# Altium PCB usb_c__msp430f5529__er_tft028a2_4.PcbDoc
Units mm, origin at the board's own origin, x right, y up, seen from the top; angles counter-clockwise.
Board outline 82 x 52 mm, 2 copper layers (Top, Bottom), stack 0 mm thick; 36 components, 35 nets, 241 pads, 100 vias.
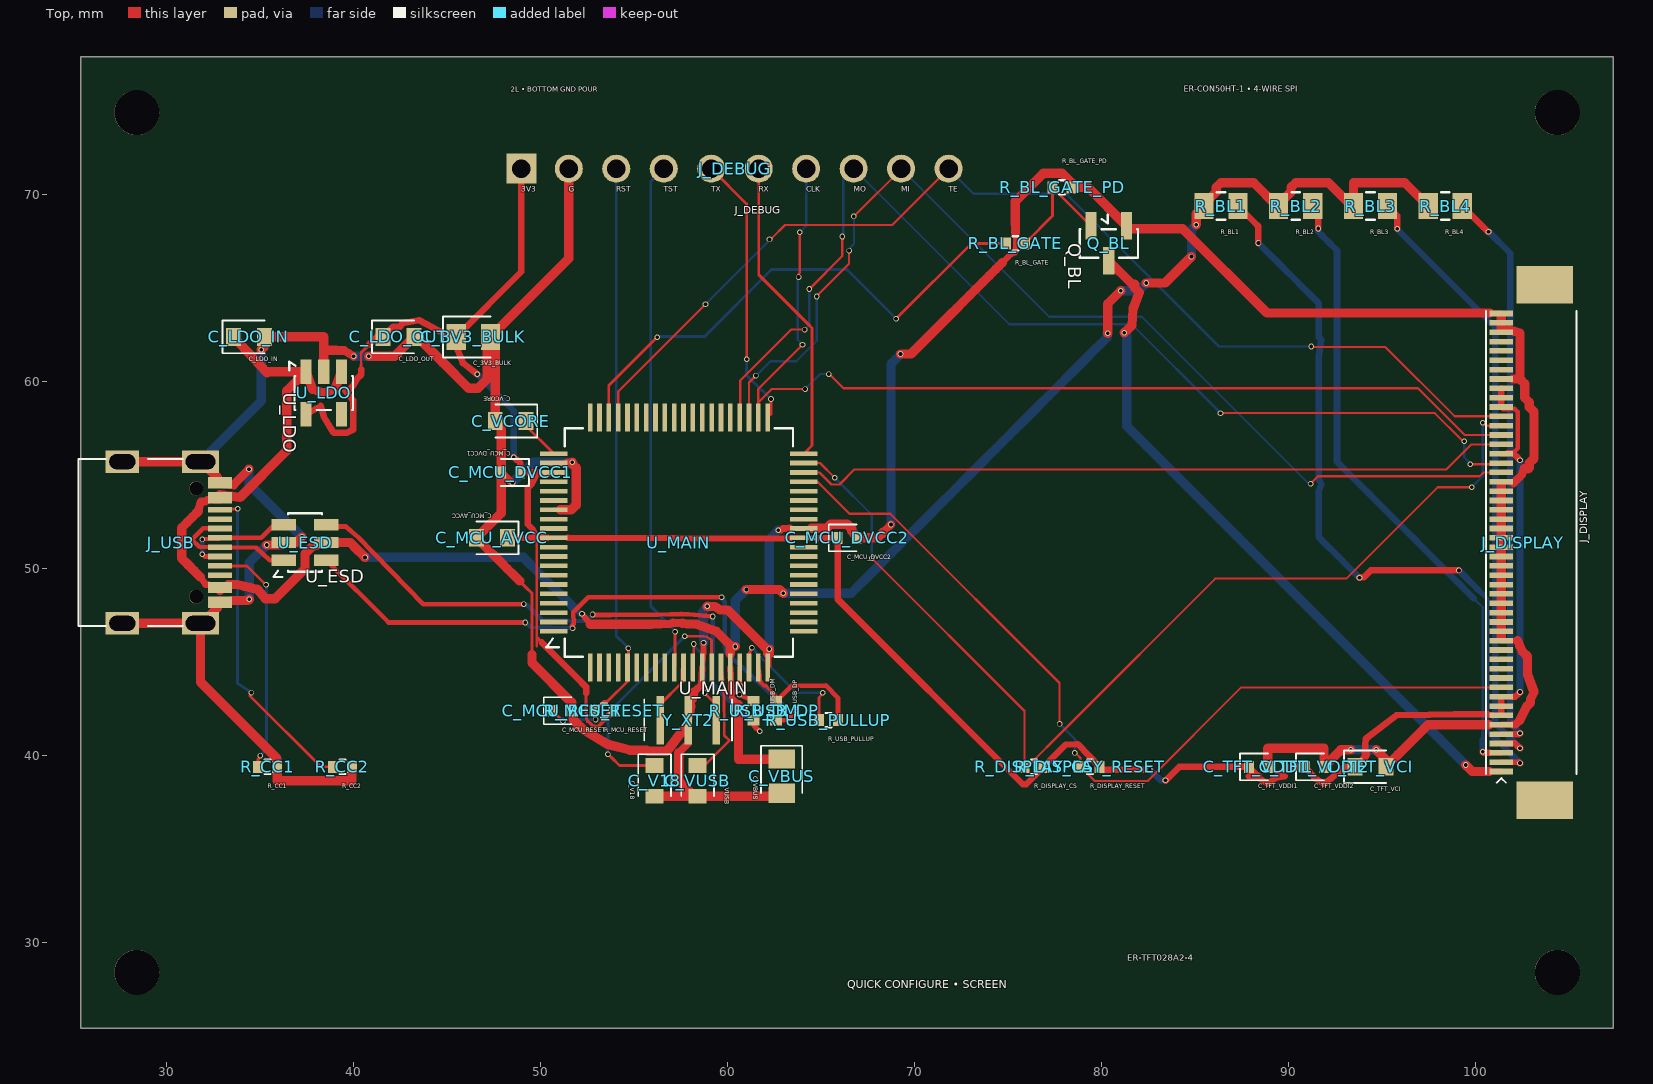
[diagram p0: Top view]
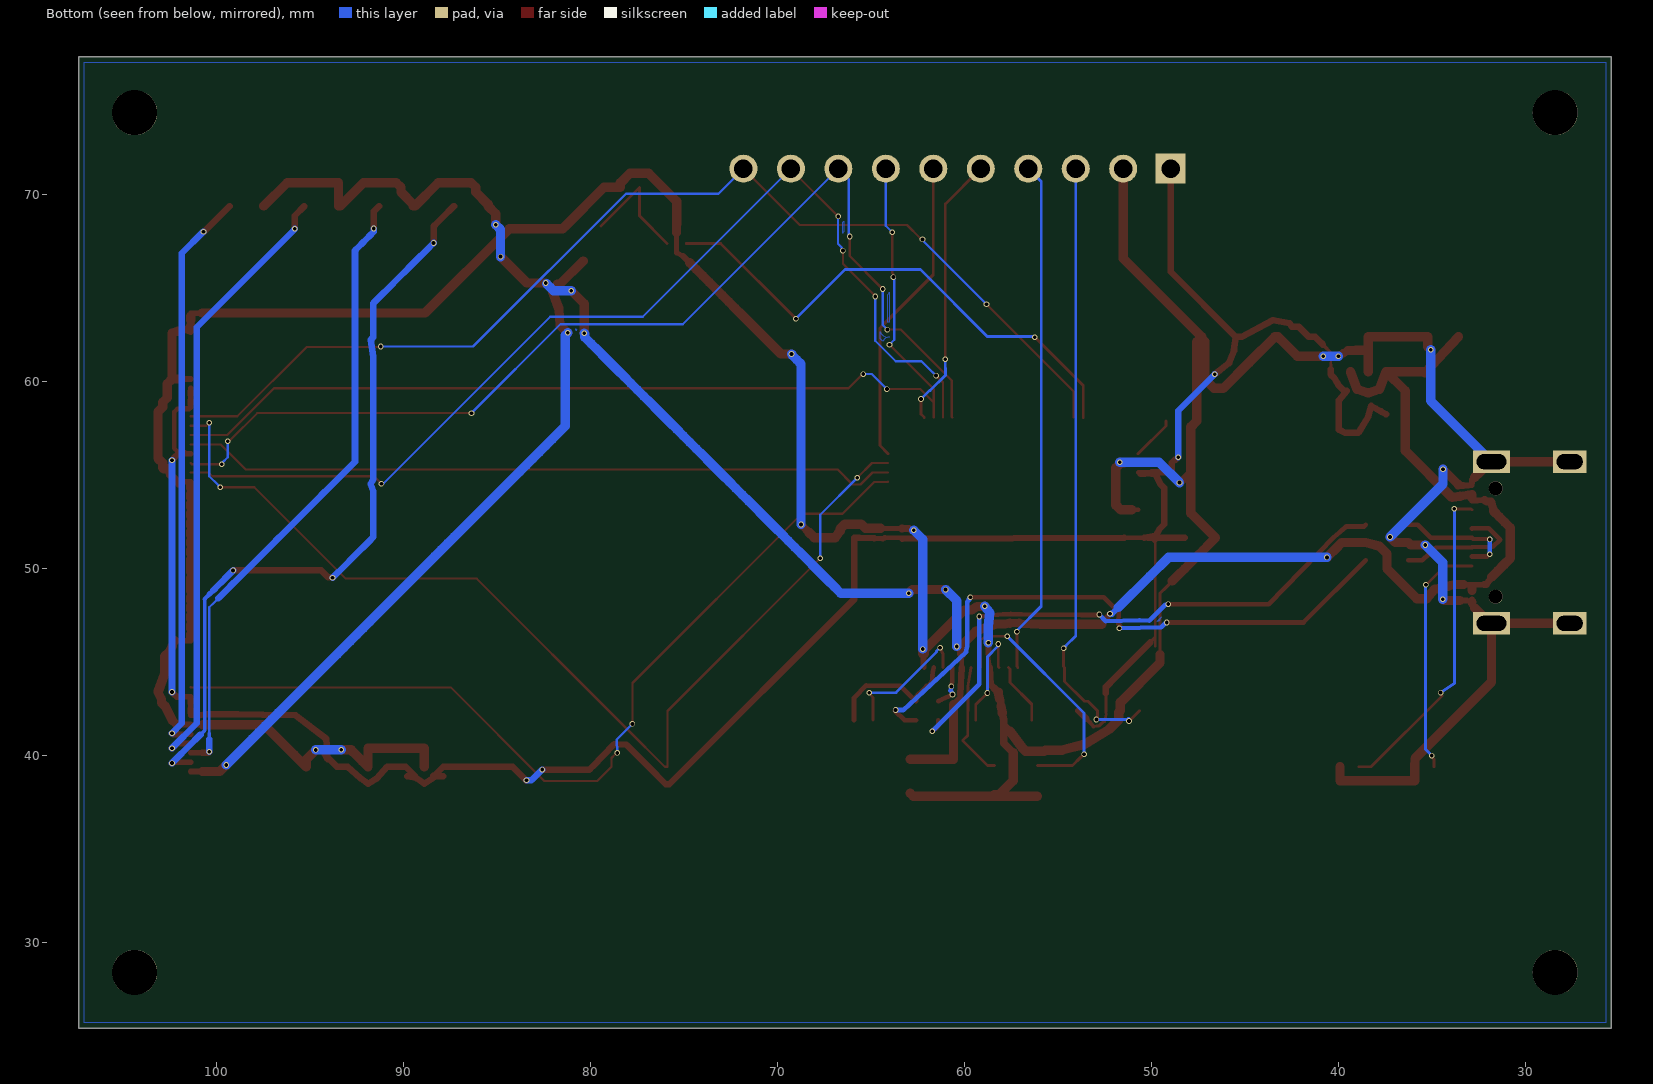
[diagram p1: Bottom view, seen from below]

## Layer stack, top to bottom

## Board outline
25.4,77.4 107.4,77.4 107.4,25.4 25.4,25.4

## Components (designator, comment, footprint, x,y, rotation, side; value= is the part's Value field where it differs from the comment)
C_3V3_BULK "" TSCIRCUIT-2.8500x1.4000mm 46.4,62.4 r0 top
C_LDO_IN "" TSCIRCUIT-2.4500x0.9500mm 34.4,62.4 r0 top
C_LDO_OUT "" TSCIRCUIT-2.4500x0.9500mm 42.4,62.4 r0 top
C_MCU_AVCC "" TSCIRCUIT-2.4500x0.9500mm 47.4,51.65 r180 top
C_MCU_DVCC1 "" TSCIRCUIT-1.5600x0.6400mm 48.4,55.15 r180 top
C_MCU_DVCC2 "" TSCIRCUIT-1.5600x0.6400mm 66.4,51.65 r0 top
C_MCU_RESET "" TSCIRCUIT-1.5600x0.6400mm 51.15,42.4 r0 top
C_TFT_VCI "" TSCIRCUIT-2.4500x0.9500mm 94.4,39.4 r0 top
C_TFT_VDDI1 "" TSCIRCUIT-1.5600x0.6400mm 88.4,39.4 r0 top
C_TFT_VDDI2 "" TSCIRCUIT-1.5600x0.6400mm 91.4,39.4 r0 top
C_V18 "" TSCIRCUIT-0.9500x2.4500mm 56.1,38.65 r270 top
C_VBUS "" TSCIRCUIT-1.4000x2.8500mm 62.9,38.9 r270 top
C_VCORE "" TSCIRCUIT-2.4500x0.9500mm 48.4,57.9 r180 top
C_VUSB "" TSCIRCUIT-0.9500x2.4500mm 58.4,38.65 r270 top
J_DEBUG "" TSCIRCUIT-24.3600x1.5000mm 60.4,71.4 r0 top
J_DISPLAY "" TSCIRCUIT-4.4500x29.5800mm 103,51.4 r90 top
J_USB "" TSCIRCUIT-6.7732x9.8502mm 30.113,51.4 r90 top
Q_BL "" TSCIRCUIT-2.5000x3.3500mm 80.4,67.4 r270 top
R_BL1 "" TSCIRCUIT-2.8500x1.4000mm 86.4,69.4 r0 top
R_BL2 "" TSCIRCUIT-2.8500x1.4000mm 90.4,69.4 r0 top
R_BL3 "" TSCIRCUIT-2.8500x1.4000mm 94.4,69.4 r0 top
R_BL4 "" TSCIRCUIT-2.8500x1.4000mm 98.4,69.4 r0 top
R_BL_GATE "" TSCIRCUIT-1.5600x0.6400mm 75.4,67.4 r0 top
R_BL_GATE_PD "" TSCIRCUIT-1.5600x0.6400mm 77.9,70.4 r0 top
R_CC1 "" TSCIRCUIT-1.5600x0.6400mm 35.4,39.4 r0 top
R_CC2 "" TSCIRCUIT-1.5600x0.6400mm 39.4,39.4 r0 top
R_DISPLAY_CS "" TSCIRCUIT-1.5600x0.6400mm 76.4,39.4 r0 top
R_DISPLAY_RESET "" TSCIRCUIT-1.5600x0.6400mm 79.4,39.4 r0 top
R_MCU_RESET "" TSCIRCUIT-1.5600x0.6400mm 53.4,42.4 r0 top
R_USB_DM "" TSCIRCUIT-0.6400x1.5600mm 61.4,42.4 r90 top
R_USB_DP "" TSCIRCUIT-0.6400x1.5600mm 62.6,42.4 r90 top
R_USB_PULLUP "" TSCIRCUIT-1.5600x0.6400mm 65.4,41.9 r0 top
U_ESD "" TSCIRCUIT-3.6000x2.5000mm 37.4,51.4 r0 top
U_LDO "" TSCIRCUIT-2.5000x3.6000mm 38.4,59.4 r270 top
U_MAIN "" TSCIRCUIT-14.8500x14.8500mm 57.4,51.4 r0 top
Y_XT2 "" TSCIRCUIT-3.4000x2.6000mm 57.9,41.9 r270 top

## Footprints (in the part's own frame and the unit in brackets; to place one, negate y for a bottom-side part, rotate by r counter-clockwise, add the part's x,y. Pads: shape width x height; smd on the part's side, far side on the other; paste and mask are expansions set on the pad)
TSCIRCUIT-0.6400x1.5600mm [mm]
  rect 0.54x0.64 smd: 1(-0.51,0) 2(0.51,0)
  silkscreen extent -0.15,-0.38 0.15,0.38
TSCIRCUIT-0.9500x2.4500mm [mm]
  rect 0.8x0.95 smd: 1(-0.825,0) 2(0.825,0)
  silkscreen extent -1.43,-0.87 0.82,0.87
TSCIRCUIT-1.4000x2.8500mm [mm]
  rect 1.025x1.4 smd: 1(-0.913,0) 2(0.913,0)
  silkscreen extent -1.62,-1.1 0.91,1.1
TSCIRCUIT-1.5600x0.6400mm [mm]
  rect 0.54x0.64 smd: 1(-0.51,0) 2(0.51,0)
  silkscreen extent -0.98,-0.72 0.51,0.72
TSCIRCUIT-2.4500x0.9500mm [mm]
  rect 0.8x0.95 smd: 1(-0.825,0) 2(0.825,0)
  silkscreen extent -1.43,-0.87 0.82,0.87
TSCIRCUIT-2.5000x3.3500mm [mm]
  rect 1.475x0.6 smd: 1(-0.938,-0.95) 2(-0.938,0.95) 3(0.937,0)
  silkscreen extent -1.54,-1.56 0.76,1.56
TSCIRCUIT-2.5000x3.6000mm [mm]
  rect 1.325x0.6 smd: 1(-1.137,-0.95) 2(-1.137,0) 3(-1.137,0.95) 4(1.138,0.95) 5(1.138,-0.95)
  silkscreen extent -1.69,-1.84 0.91,1.56
TSCIRCUIT-2.8500x1.4000mm [mm]
  rect 1.025x1.4 smd: 1(-0.913,0) 2(0.913,0)
  silkscreen extent -1.63,-1.1 0.91,1.1
TSCIRCUIT-3.4000x2.6000mm [mm]
  rect 2.6x0.4 smd: 1(0,1.5) 2(0,0) 3(0,-1.5)
  silkscreen extent -1.1,-2.35 1.1,2.35
TSCIRCUIT-3.6000x2.5000mm [mm]
  rect 1.325x0.6 smd: 1(-1.137,-0.95) 2(-1.137,0) 3(-1.137,0.95) 4(1.138,0.95) 5(1.138,0) 6(1.138,-0.95)
  silkscreen extent -1.69,-1.84 0.91,1.56
TSCIRCUIT-4.4500x29.5800mm [mm]
  rect 0.3x1.25 smd: 1(-12.25,1.6) 2(-11.75,1.6) 3(-11.25,1.6) 4(-10.75,1.6) 5(-10.25,1.6) 6(-9.75,1.6) 7(-9.25,1.6) 8(-8.75,1.6) 9(-8.25,1.6) 10(-7.75,1.6) 11(-7.25,1.6) 12(-6.75,1.6) 13(-6.25,1.6) 14(-5.75,1.6) 15(-5.25,1.6) 16(-4.75,1.6) 17(-4.25,1.6) 18(-3.75,1.6) 19(-3.25,1.6) 20(-2.75,1.6) 21(-2.25,1.6) 22(-1.75,1.6) 23(-1.25,1.6) 24(-0.75,1.6) 25(-0.25,1.6) 26(0.25,1.6) 27(0.75,1.6) 28(1.25,1.6) 29(1.75,1.6) 30(2.25,1.6) 31(2.75,1.6) 32(3.25,1.6) 33(3.75,1.6) 34(4.25,1.6) 35(4.75,1.6) 36(5.25,1.6) 37(5.75,1.6) 38(6.25,1.6) 39(6.75,1.6) 40(7.25,1.6) 41(7.75,1.6) 42(8.25,1.6) 43(8.75,1.6) 44(9.25,1.6) 45(9.75,1.6) 46(10.25,1.6) 47(10.75,1.6) 48(11.25,1.6) 49(11.75,1.6) 50(12.25,1.6)
  rect 2x3 smd: 51(13.79,-0.725) 52(-13.79,-0.725)
  silkscreen extent -12.85,-2.43 12.4,2.42
TSCIRCUIT-6.7732x9.8502mm [mm]
  rect 0.3x1.3 smd: 1(-3.35,-2.737) 2(-3.05,-2.737) 3(-2.55,-2.737) 4(-2.25,-2.737) 5(-1.75,-2.737) 6(-1.25,-2.737) 7(-0.75,-2.737) 8(-0.25,-2.737) 9(0.25,-2.737) 10(0.75,-2.737) 11(1.25,-2.737) 12(1.75,-2.737) 13(2.55,-2.737) 14(2.25,-2.737) 15(3.35,-2.737) 16(3.05,-2.737)
  rect 1.2x2 hole 0.8 slot 1.6 at 90 deg: 17(-4.325,-1.693) 18(4.325,-1.693)
  rect 1.2x1.8 hole 0.8 slot 1.4 at 90 deg: 19(4.325,2.487) 20(-4.325,2.487)
  round 0.75 hole 0.75 unplated: NPTH-1(-2.9,-1.468) NPTH-2(2.9,-1.468)
  silkscreen extent -4.47,-0.75 4.47,4.83
TSCIRCUIT-14.8500x14.8500mm [mm]
  rect 1.475x0.25 smd: 1(-6.687,-4.75) 2(-6.687,-4.25) 3(-6.687,-3.75) 4(-6.687,-3.25) 5(-6.687,-2.75) 6(-6.687,-2.25) 7(-6.687,-1.75) 8(-6.687,-1.25) 9(-6.687,-0.75) 10(-6.687,-0.25) 11(-6.687,0.25) 12(-6.687,0.75) 13(-6.687,1.25) 14(-6.687,1.75) 15(-6.687,2.25) 16(-6.687,2.75) 17(-6.687,3.25) 18(-6.687,3.75) 19(-6.687,4.25) 20(-6.687,4.75) 41(6.687,4.75) 42(6.687,4.25) 43(6.687,3.75) 44(6.687,3.25) 45(6.687,2.75) 46(6.687,2.25) 47(6.687,1.75) 48(6.687,1.25) 49(6.687,0.75) 50(6.687,0.25) 51(6.687,-0.25) 52(6.687,-0.75) 53(6.687,-1.25) 54(6.687,-1.75) 55(6.687,-2.25) 56(6.687,-2.75) 57(6.687,-3.25) 58(6.687,-3.75) 59(6.687,-4.25) 60(6.687,-4.75)
  rect 0.25x1.475 smd: 21(-4.75,6.687) 22(-4.25,6.687) 23(-3.75,6.687) 24(-3.25,6.687) 25(-2.75,6.687) 26(-2.25,6.687) 27(-1.75,6.687) 28(-1.25,6.687) 29(-0.75,6.687) 30(-0.25,6.687) 31(0.25,6.687) 32(0.75,6.687) 33(1.25,6.687) 34(1.75,6.687) 35(2.25,6.687) 36(2.75,6.687) 37(3.25,6.687) 38(3.75,6.687) 39(4.25,6.687) 40(4.75,6.687) 61(4.75,-6.687) 62(4.25,-6.687) 63(3.75,-6.687) 64(3.25,-6.687) 65(2.75,-6.687) 66(2.25,-6.687) 67(1.75,-6.687) 68(1.25,-6.687) 69(0.75,-6.687) 70(0.25,-6.687) 71(-0.25,-6.687) 72(-0.75,-6.687) 73(-1.25,-6.687) 74(-1.75,-6.687) 75(-2.25,-6.687) 76(-2.75,-6.687) 77(-3.25,-6.687) 78(-3.75,-6.687) 79(-4.25,-6.687) 80(-4.75,-6.687)
  silkscreen extent -7.09,-6.11 6.11,6.11
TSCIRCUIT-24.3600x1.5000mm [mm]
  rect 1.6x1.6 hole 1: 1(-11.43,0)
  round 1.5 hole 1: 2(-8.89,0) 3(-6.35,0) 4(-3.81,0) 5(-1.27,0) 6(1.27,0) 7(3.81,0) 8(6.35,0) 9(8.89,0) 10(11.43,0)

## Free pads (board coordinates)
  round 2.4 hole 2.4 unplated: NPTH-3(28.4,28.4) NPTH-4(104.4,28.4) NPTH-5(28.4,74.4) NPTH-6(104.4,74.4)

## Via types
v1: diameter 0.3, hole 0.2, Top to Bottom, 100 vias

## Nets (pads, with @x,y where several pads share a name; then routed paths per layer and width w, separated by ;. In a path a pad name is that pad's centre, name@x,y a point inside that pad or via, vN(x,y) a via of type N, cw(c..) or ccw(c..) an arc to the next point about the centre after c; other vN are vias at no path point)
".J_DEBUG > .pin4 to .U_MAIN > .pin71": J_DEBUG.4 U_MAIN.71 | length 27.5
  Top w0.15: U_MAIN.71 57.197,44.759 v1(57.197,46.62)
  Bottom w0.15: J_DEBUG.4 55.895,70.705 55.895,48.203 55.895,47.992 57.198,46.689 57.198,46.676 v1(57.197,46.62)
".J_DEBUG > .pin5 to .U_MAIN > .pin40": J_DEBUG.5 U_MAIN.40 | length 14.7
  Top w0.15: J_DEBUG.5 61.026,69.504 61.026,61.435 v1@61.026,61.2 ; U_MAIN.40 62.329,58.266 v1(62.329,59.08)
  Bottom w0.15: v1(61.026,61.2) 61.023,60.347 61.837,59.536 61.872,59.537 62.2,59.209 v1(62.329,59.08)
".J_DEBUG > .pin6 to .U_MAIN > .pin41": J_DEBUG.6 U_MAIN.41 | length 16.6
  Top w0.15: J_DEBUG.6 61.67,65.728 64.377,63.021 64.521,62.878 64.521,56.721 64.521,56.583 U_MAIN.41
BACKLIGHT_ANODE_1: J_DISPLAY.2 R_BL1.2 | length 40.9
  Top w0.3: J_DISPLAY.2 101.71,39.65 102.019,39.65 v1@102.329,39.65
  Top w0.35: R_BL1.2 87.531,69.182 87.749,68.964 87.967,68.746 88.185,68.528 88.403,68.31 88.403,68.015 88.403,67.719 v1(88.403,67.424) ; v1(93.81,49.513) 93.829,49.532 94.038,49.532 94.225,49.72 94.413,49.907 94.75,49.907 95.086,49.907 95.423,49.907 95.76,49.907 96.097,49.907 96.434,49.907 96.771,49.907 97.108,49.907 97.445,49.907 97.782,49.907 98.119,49.907 98.456,49.907 98.793,49.907 v1(99.13,49.907) ; v1@102.329,39.65 102.379,39.6 v1(102.4,39.6)
  Bottom w0.188: 100.657,48.376 100.657,48.041 100.657,47.706 100.657,47.371 100.657,47.036 100.657,46.702 100.657,46.367 100.657,46.032 100.657,45.697 100.657,45.362 100.657,45.027 100.657,44.692 100.657,44.357 100.657,44.023 100.657,43.688 100.657,43.353 100.657,43.018 100.657,42.683 100.657,42.348 100.657,42.013 100.657,41.678 100.657,41.343 100.874,41.126
  Bottom w0.238: 100.421,48.612 100.657,48.376
  Bottom w0.275: 100.185,48.847 100.421,48.612
  Bottom w0.35: v1(88.403,67.424) 88.447,67.38 88.692,67.135 88.936,66.891 89.18,66.647 89.424,66.403 89.668,66.159 89.912,65.915 90.156,65.671 90.4,65.427 90.644,65.183 90.888,64.939 91.132,64.695 91.376,64.451 91.62,64.206 91.62,64.101 91.62,63.756 91.62,63.412 91.62,63.067 91.62,62.723 91.62,62.379 91.775,62.25 91.62,61.346 91.62,61.001 91.62,60.657 91.62,60.312 91.62,59.968 91.62,59.624 91.62,59.279 91.62,58.935 91.62,58.59 91.62,58.246 91.62,57.902 91.62,57.557 91.62,57.213 91.62,56.868 91.62,56.524 91.62,56.18 91.62,55.835 91.62,55.491 91.62,55.147 91.62,54.802 91.775,54.55 91.62,54.113 91.62,53.769 91.62,53.425 91.62,53.08 91.62,52.736 91.62,52.391 91.62,52.047 91.62,51.703 91.864,51.459 92.107,51.216 92.35,50.973 92.594,50.729 92.837,50.486 93.08,50.243 93.323,50 93.567,49.756 v1(93.81,49.513) ; v1(99.13,49.907) 99.243,49.794 99.243,49.79 99.478,49.554 99.714,49.318 99.95,49.083 100.185,48.847 ; 100.874,41.126 101.092,40.908 101.31,40.69 101.528,40.472 101.746,40.254 101.964,40.036 102.182,39.818 v1(102.4,39.6)
BACKLIGHT_ANODE_2: J_DISPLAY.3 R_BL2.2 | length 34
  Top w0.3: 100.769,40.15 101.084,40.15 J_DISPLAY.3
  Top w0.35: R_BL2.2 91.456,69.257 91.6,69.113 91.6,68.808 91.6,68.503 v1(91.6,68.198) ; v1(100.4,40.2) 100.413,40.187 100.416,40.187 100.453,40.15 100.769,40.15
  Bottom w0.12: 99.913,48.417 100.157,48.173 100.4,47.93 100.4,47.594
  Bottom w0.125: 100.4,41.208 100.4,41.544 100.4,41.88 100.4,42.217 100.4,42.553 100.4,42.889 100.4,43.225 100.4,43.561 100.4,43.897 100.4,44.233 100.4,44.569 100.4,44.905 100.4,45.241 100.4,45.577 100.4,45.913 100.4,46.25 100.4,46.586 100.4,46.922 100.4,47.258 100.4,47.594
  Bottom w0.188: 100.4,40.872 100.4,41.208
  Bottom w0.35: v1(91.6,68.198) 91.6,68.025 91.802,67.823 92.004,67.622 92.205,67.42 92.407,67.218 92.609,67.016 92.609,66.674 92.609,66.332 92.609,65.989 92.609,65.647 92.609,65.305 92.609,64.962 92.609,64.62 92.609,64.278 92.609,63.936 92.609,63.593 92.609,63.251 92.609,62.909 92.609,62.566 92.609,62.224 92.609,61.882 92.609,61.54 92.609,61.197 92.609,60.855 92.609,60.513 92.609,60.171 92.609,59.828 92.609,59.486 92.609,59.144 92.609,58.801 92.609,58.459 92.609,58.117 92.609,57.775 92.609,57.432 92.609,57.09 92.609,56.748 92.609,56.405 92.609,56.063 92.609,55.721 92.853,55.477 93.096,55.234 93.34,54.99 93.583,54.747 93.826,54.504 94.07,54.26 94.313,54.017 94.557,53.773 94.8,53.53 95.044,53.286 95.287,53.043 95.531,52.799 95.774,52.556 96.018,52.312 96.261,52.069 96.505,51.825 96.748,51.582 96.992,51.339 97.235,51.095 97.478,50.852 97.722,50.608 97.965,50.365 98.209,50.121 98.452,49.878 98.696,49.634 98.939,49.391 99.183,49.147 99.426,48.904 99.67,48.66 99.913,48.417 ; v1(100.4,40.2) 100.4,40.536 100.4,40.872
BACKLIGHT_ANODE_3: J_DISPLAY.4 R_BL3.2 | length 33
  Top w0.3: J_DISPLAY.4 101.494,40.65 101.588,40.65 101.681,40.65 101.775,40.65 101.869,40.65 101.963,40.65 102.025,40.65 102.056,40.65
  Top w0.35: R_BL3.2 95.829,68.884 v1(95.829,68.18) ; 102.056,40.65 102.129,40.65 102.144,40.635 102.321,40.458 102.342,40.458 v1(102.4,40.4)
  Bottom w0.35: v1(95.829,68.18) 95.858,68.151 95.858,68.132 101.071,62.919 101.071,52.598 101.071,41.729 v1(102.4,40.4)
BACKLIGHT_ANODE_4: J_DISPLAY.5 R_BL4.2 | length 30.5
  Top w0.3: J_DISPLAY.5 101.494,41.15 101.588,41.15 101.681,41.15 101.775,41.15 101.869,41.15 101.963,41.15 102.025,41.15 102.056,41.15
  Top w0.35: R_BL4.2 100.686,68.027 v1(100.716,68.027) ; 102.056,41.15 102.15,41.15 102.329,41.15 102.379,41.2 v1(102.4,41.2)
  Bottom w0.35: v1(100.716,68.027) 100.736,68.007 101.872,66.871 101.872,66.73 101.872,41.728 v1(102.4,41.2)
BACKLIGHT_CATHODE: J_DISPLAY.1 Q_BL.3 | length 37.6
  Top w0.3: 100.775,39.15 100.837,39.15 100.931,39.15 101.025,39.15 101.119,39.15 101.213,39.15 101.306,39.15 J_DISPLAY.1
  Top w0.475: 100.744,39.15 100.775,39.15
  Top w0.5: Q_BL.3 81.649,65.213 81.786,65.213 81.786,65.014 82.025,64.775 81.697,63.891 81.667,63.451 81.638,63.01 81.429,62.819 v1(81.22,62.627) ; v1(99.495,39.498) 99.53,39.463 99.843,39.15 100.247,39.15 100.65,39.15 100.744,39.15
  Bottom w0.5: v1(81.22,62.627) 81.362,62.485 81.362,61.999 81.362,61.514 81.362,61.028 81.362,60.543 81.362,60.058 81.362,59.572 81.362,59.087 81.362,58.601 81.362,58.116 81.362,57.631 81.711,57.282 82.06,56.933 82.409,56.584 82.757,56.236 83.106,55.887 83.455,55.538 83.803,55.19 84.152,54.841 84.501,54.492 84.849,54.144 85.198,53.795 85.547,53.446 85.896,53.097 86.244,52.749 86.593,52.4 86.942,52.051 87.29,51.703 87.639,51.354 87.988,51.005 88.336,50.657 88.685,50.308 89.034,49.959 89.383,49.61 89.731,49.262 90.08,48.913 90.429,48.564 90.777,48.216 91.126,47.867 91.475,47.518 91.824,47.169 92.172,46.821 92.521,46.472 92.87,46.123 93.218,45.775 93.567,45.426 93.916,45.077 94.264,44.729 94.613,44.38 94.962,44.031 95.311,43.682 95.659,43.334 96.008,42.985 96.357,42.636 96.705,42.288 97.054,41.939 97.403,41.59 97.751,41.242 98.1,40.893 98.449,40.544 98.798,40.195 99.146,39.847 v1(99.495,39.498)
BACKLIGHT_GATE: Q_BL.1 R_BL_GATE.2 R_BL_GATE_PD.1 | length 6.5
  Top w0.15: R_BL_GATE.2 77.39,68.88 R_BL_GATE_PD.1 79.45,68.34 Q_BL.1
BACKLIGHT_PWM: R_BL_GATE.1 U_MAIN.23 | length 28.3
  Top w0.15: U_MAIN.23 53.65,59.794 v1(56.236,62.38) ; v1(69.021,63.376) 69.055,63.41 73.045,67.4 R_BL_GATE.1
  Bottom w0.15: v1(56.236,62.38) 56.279,62.423 56.343,62.423 58.782,62.423 62.359,66.001 66.396,66.001 v1(69.021,63.376)
DISPLAY_CS_N: J_DISPLAY.38 R_DISPLAY_CS.1 U_MAIN.42 | length 56.5
  Top w0.12: U_MAIN.42 64.952,55.65 v1(65.733,54.869) ; v1(67.713,50.559) 67.746,50.526 75.89,42.382 R_DISPLAY_CS.1 76.03,39.4 78.059,41.429 86.098,49.468 93.105,49.468 97.994,54.357 v1(99.823,54.357) ; v1(100.4,57.8) 100.433,57.767 100.449,57.767 100.566,57.65 J_DISPLAY.38
  Bottom w0.12: v1(65.733,54.869) 65.753,54.849 67.713,52.889 v1(67.713,50.559) ; v1(99.823,54.357) 99.942,54.476 99.942,54.491 100.4,54.948 v1(100.4,57.8)
DISPLAY_DC: J_DISPLAY.36 U_MAIN.43 | length 38.5
  Top w0.12: U_MAIN.43 64.924,55.15 65.569,54.505 65.989,54.505 66.046,54.561 66.787,55.303 98.458,55.303 99.805,56.65 J_DISPLAY.36
DISPLAY_MISO: J_DEBUG.9 J_DISPLAY.33 U_MAIN.38 | length 56.8
  Top w0.12: U_MAIN.38 61.15,59.961 v1(61.521,60.332) ; v1(64.77,64.563) 64.878,64.671 64.878,64.693 66.504,66.319 v1(66.504,67.017) ; v1(66.762,68.847) 66.83,68.915 66.839,68.915 69.29,71.367 J_DEBUG.9 ; v1(91.196,54.55) 91.587,54.941 100.239,54.941 100.447,55.15 J_DISPLAY.33
  Bottom w0.12: v1(61.521,60.332) 61.674,60.485 61.682,60.485 62.3,61.102 63.673,61.102 64.77,62.199 v1(64.77,64.563) ; v1(66.504,67.017) 66.571,67.084 66.571,67.177 66.762,67.368 v1(66.762,68.847) ; J_DEBUG.9 77.208,63.482 81.76,63.482 82.16,63.482 91.069,54.574 91.172,54.574 v1(91.196,54.55)
DISPLAY_MOSI: J_DEBUG.8 J_DISPLAY.34 U_MAIN.37 | length 58
  Top w0.12: U_MAIN.37 60.689,58.126 60.689,60.068 63.413,62.792 v1(64.126,62.792) ; v1(64.376,64.96) 64.408,64.992 66.145,66.729 v1(66.145,67.77) ; v1(86.377,58.322) 97.837,58.322 99.278,56.881 99.356,56.881 v1(99.42,56.817) ; v1(99.743,55.586) 101.336,55.586 J_DISPLAY.34
  Bottom w0.12: v1(64.126,62.792) 64.144,62.81 64.376,63.042 v1(64.376,64.96) ; v1(66.145,67.77) 66.194,67.819 66.194,67.88 66.194,70.844 J_DEBUG.8 75.072,63.078 81.553,63.078 81.621,63.078 86.345,58.354 v1(86.377,58.322) ; v1(99.42,56.817) 99.42,55.957 99.694,55.683 99.694,55.635 v1(99.743,55.586)
DISPLAY_RESET_N: J_DISPLAY.10 R_DISPLAY_RESET.1 U_MAIN.44 | length 48
  Top w0.12: U_MAIN.44 64.1,54.638 64.83,54.638 66.528,52.941 68.709,52.941 77.768,43.882 v1(77.768,41.695) ; v1(78.579,40.145) 78.689,40.111 78.689,40.067 78.89,39.866 R_DISPLAY_RESET.1 79.647,38.643 82.479,38.638 87.482,43.65 J_DISPLAY.10
  Bottom w0.12: v1(77.768,41.695) 77.831,41.632 77.834,41.632 78.6,40.866 v1(78.579,40.145)
DISPLAY_SCLK: J_DEBUG.7 J_DISPLAY.37 U_MAIN.39 | length 57.1
  Top w0.12: v1(63.804,65.6) 63.817,65.613 63.817,65.766 63.867,65.816 v1(63.867,67.994) ; v1(64.016,61.983) 61.65,59.617 U_MAIN.39 61.65,58.893 61.862,59.105 62.366,59.609 v1(64.151,59.609) ; v1(65.417,60.41) 65.453,60.374 65.486,60.374 66.207,59.653 96.937,59.653 99.439,57.15 J_DISPLAY.37
  Bottom w0.12: v1(63.804,65.6) 63.755,65.551 63.755,62.373 63.755,62.244 v1(64.016,61.983) ; v1(63.867,67.994) 63.897,68.024 63.897,68.03 64.21,68.343 J_DEBUG.7 ; v1(64.151,59.609) 64.217,59.675 64.223,59.675 64.958,60.41 v1(65.417,60.41)
DISPLAY_TE: J_DEBUG.10 J_DISPLAY.39 U_MAIN.24 | length 59.1
  Top w0.12: U_MAIN.24 54.15,59.473 v1(58.821,64.144) ; v1(62.246,67.614) 62.316,67.684 62.37,67.684 63.077,68.391 68.821,68.391 J_DEBUG.10 ; v1(91.226,61.886) 91.248,61.864 91.439,61.864 95.189,61.864 98.903,58.15 J_DISPLAY.39
  Bottom w0.12: v1(58.821,64.144) 58.917,64.24 58.917,64.245 62.246,67.575 v1(62.246,67.614) ; J_DEBUG.10 73.168,70.062 78.114,70.062 86.291,61.886 v1(91.226,61.886)
GND: C_3V3_BULK.2 C_LDO_IN.2 C_LDO_OUT.2 C_MCU_AVCC.2 C_MCU_DVCC1.2 C_MCU_DVCC2.2 C_MCU_RESET.2 C_TFT_VCI.2 C_TFT_VDDI1.2 C_TFT_VDDI2.2 C_V18.2 C_VBUS.2 C_VCORE.2 C_VUSB.2 J_DEBUG.2 J_DISPLAY.6 J_DISPLAY.15 J_DISPLAY.16 J_DISPLAY.17 J_DISPLAY.18 J_DISPLAY.19 J_DISPLAY.20 J_DISPLAY.21 J_DISPLAY.22 J_DISPLAY.23 J_DISPLAY.24 J_DISPLAY.25 J_DISPLAY.26 J_DISPLAY.27 J_DISPLAY.28 J_DISPLAY.29 J_DISPLAY.30 J_DISPLAY.31 J_DISPLAY.32 J_DISPLAY.43 J_DISPLAY.48 J_DISPLAY.49 J_DISPLAY.50 J_USB.1 J_USB.2 J_USB.15 J_USB.16 J_USB.17 J_USB.18 J_USB.19 J_USB.20 Q_BL.2 R_BL_GATE_PD.2 R_CC1.2 R_CC2.2 U_ESD.2 U_LDO.2 U_MAIN.14 U_MAIN.19 U_MAIN.49 U_MAIN.61 U_MAIN.68 Y_XT2.2 | length 253.7
  Top w0.175: 48.883,49.342 49.212,49.013 49.542,48.683 49.542,48.522 49.542,48.078 49.542,47.633 49.542,47.188 49.542,46.743 49.542,46.298 49.542,45.853 49.542,45.408
  Top w0.25: U_MAIN.14 U_MAIN.14@51.061,53.15 ; U_MAIN.68 58.723,45.203 U_MAIN.68@58.723,45.45 ; U_MAIN.61@62.15,45.448 62.15,45.369 62.15,45.275 62.15,45.181 62.15,45.087 62.15,44.994 62.15,44.9 62.15,44.806 U_MAIN.61 62.235,44.797 U_MAIN.61@62.235,45.45 ; U_MAIN.49@63.35,52.15 63.431,52.15 63.525,52.15 63.619,52.15 63.712,52.15 63.806,52.15 63.9,52.15 63.994,52.15 U_MAIN.49 ; U_MAIN.19 51.45,55.65 51.369,55.65 51.275,55.65 51.181,55.65 51.088,55.65 50.994,55.65 50.9,55.65 50.806,55.65 U_MAIN.19
  Top w0.259: U_MAIN.61@62.149,45.45 U_MAIN.61@62.15,45.448
  Top w0.269: U_MAIN.49 U_MAIN.49@64.494,52.155
  Top w0.275: J_USB.1@32.849,48.2 J_USB.2 ; 75.051,66.718 75.4,66.9 75.4,67.209 75.4,67.519 75.4,67.971
  Top w0.288: J_USB.15@32.849,54.6 J_USB.16 J_USB.16@32.945,54.461
  Top w0.3: J_USB.1@32.699,47.9 J_USB.1 J_USB.2@32.849,48.2 ; 32.699,54.9 J_USB.15 J_USB.16@32.849,54.6 ; J_USB.2 33,48.251 33.125,48.295 33.499,48.295 ; J_USB.16@32.945,54.461 33.037,54.45 J_USB.16@33.318,54.45 ; 100.775,41.65 101.025,41.65 101.306,41.65 J_DISPLAY.6 ; 100.775,63.675 101.375,63.675 J_DISPLAY.50 J_DISPLAY.50@101.4,63.5 ; J_DISPLAY.15@101.4,46.3 J_DISPLAY.15 101.672,46.15 101.974,46.15 102.275,46.15 ; J_DISPLAY.16@101.4,46.5 J_DISPLAY.16 J_DISPLAY.16@101.4,46.8 ; J_DISPLAY.17@101.4,47 J_DISPLAY.17 101.4,47.3 ; J_DISPLAY.18@101.4,47.5 J_DISPLAY.18 J_DISPLAY.18@101.4,47.8 ; J_DISPLAY.19@101.4,48 J_DISPLAY.19 101.4,48.3 ; J_DISPLAY.20@101.4,48.5 J_DISPLAY.20 ; J_DISPLAY.21@101.4,49 J_DISPLAY.21 ; J_DISPLAY.22@101.4,49.5 J_DISPLAY.22 J_DISPLAY.22@101.4,49.8 ; J_DISPLAY.23 101.4,50.3 ; 101.4,50.8 J_DISPLAY.24 ; J_DISPLAY.25@101.4,51 J_DISPLAY.25 J_DISPLAY.25@101.4,51.3 ; J_DISPLAY.26@101.4,51.5 J_DISPLAY.26 J_DISPLAY.26@101.4,51.8 ; 101.4,52 J_DISPLAY.27 101.4,52.3 ; J_DISPLAY.28@101.4,52.5 J_DISPLAY.28 101.4,52.8 ; J_DISPLAY.29@101.4,53 J_DISPLAY.29 101.4,53.3 ; J_DISPLAY.30@101.4,53.5 J_DISPLAY.30 101.4,53.8 ; J_DISPLAY.31@101.4,54 J_DISPLAY.31 J_DISPLAY.31@101.4,54.3 ; J_DISPLAY.32@101.4,54.5 J_DISPLAY.32 101.663,54.65 102.056,54.572 ; 101.4,62.8 J_DISPLAY.48 101.8,62.8 ; J_DISPLAY.49@101.4,63 J_DISPLAY.49 J_DISPLAY.49@101.4,63.3 ; J_DISPLAY.20 101.4,48.8 J_DISPLAY.20 ; J_DISPLAY.24 101.4,50.5 J_DISPLAY.24 ; J_DISPLAY.43@101.838,60.15 J_DISPLAY.43 J_DISPLAY.43@101.838,60.15 ; J_DISPLAY.43@101.838,60.15 102.025,60.15 J_DISPLAY.43@101.838,60.15
  Top w0.312: 58.723,45.45 58.723,45.621 v1(58.723,46.038)
  Top w0.325: v1@48.426,54.614 v1(48.5,54.605) ; v1(62.72,52.059) 62.768,52.067 62.872,52.067 ; 74.702,66.369 75.051,66.718 ; J_DISPLAY.6 101.783,41.658 J_DISPLAY.6@102.025,41.663
  Top w0.33: U_MAIN.68@58.61,43.975 58.625,44.256 U_MAIN.68
  Top w0.35: 62.872,52.067 62.956,52.15 63.338,52.15
  Top w0.375: 58.4,43.6 58.6,43.8 U_MAIN.68@58.61,43.975
  Top w0.4: J_USB.16@33.318,54.45 33.599,54.45 ; C_MCU_DVCC1.2 48.158,54.882 v1@48.426,54.614 ; 57.4,40.15 57.9,40.65 Y_XT2.2 ; 57.565,41.3 57.9,41.635 Y_XT2.2 ; Y_XT2.2@57.975,42.275 Y_XT2.2 ; Y_XT2.2@58.05,42.65 58.05,42.95 58.125,43.025 ; 58.2,43.4 58.4,43.6
  Top w0.425: 63.338,52.15 U_MAIN.49@63.35,52.15
  Top w0.437: 39.494,61.681 39.745,61.524 v1(39.996,61.367) ; 68.342,51.961 68.652,52.271 v1(68.745,52.364) ; 100.744,41.65 100.775,41.65 ; 102.056,54.572 102.275,54.791 102.494,55.009
  Top w0.45: 33.599,54.45 33.599,54.523 ; 102.025,41.663 102.166,41.666 102.384,41.884 ; 102.494,55.009 102.615,55.339
  Top w0.475: 33.599,54.523 v1(34.401,55.325) ; 39.056,61.681 39.494,61.681 ; 75.4,67.971 75.4,68.423 ; 101.8,62.8 102.1,62.7 ; 102.275,46.15 102.394,45.866 ; 102.025,60.15 102.275,60.15 102.025,60.15
  Top w0.5: J_USB.20 J_USB.17 ; J_USB.19 J_USB.18 31.874,55.725 32.474,55.125 32.699,54.9 ; J_USB.1@32.699,47.9 32.474,47.675 31.874,47.075 J_USB.17 ; 33.499,48.295 34.343,48.295 v1(34.418,48.37) ; v1(35.058,61.713) 35.225,61.88 C_LDO_IN.2 38.4,62.4 U_LDO.2 38.4,61.681 39.056,61.681 ; v1(35.353,51.265) 36.127,51.265 U_ESD.2 36.944,51.4 v1(37.239,51.695) ; R_CC2.2 39.91,38.65 35.91,38.65 R_CC1.2 35.9,39.84 31.806,43.935 J_USB.17 ; v1(40.804,61.361) 40.809,61.366 40.903,61.366 41.333,61.366 41.762,61.366 42.191,61.366 42.536,61.711 42.88,62.055 C_LDO_OUT.2 43.4,62.4 44.775,61.025 46.15,59.65 46.65,59.65 47.15,60.15 47.15,62.15 47.4,62.4 C_3V3_BULK.2 ; 48.883,49.342 48.553,49.672 48.223,50.002 47.894,50.331 47.564,50.661 47.234,50.991 46.905,51.32 C_MCU_AVCC.2 47.89,52.965 C_MCU_DVCC1.2 47.89,57.585 C_VCORE.2 47.575,62.138 C_3V3_BULK.2 ; 49.542,45.408 49.542,44.963 51.66,42.845 C_MCU_RESET.2 51.742,42.318 51.742,41.933 52.275,41.4 53.578,40.609 54.781,40.295 55.226,40.295 55.671,40.295 55.733,40.233 56.733,40.233 56.9,40.4 57.565,41.3 ; U_MAIN.14@51.061,53.15 51.65,53.15 51.9,53.4 51.9,55.4 51.65,55.65 51.45,55.65 51.463,55.65 51.645,55.65 51.693,55.697 51.697,55.697 v1(51.7,55.7) ; J_DEBUG.2 51.51,66.597 C_3V3_BULK.2 ; C_V18.2 C_VUSB.2 ; 57.4,40.15 57.4,38.65 58.15,37.9 58.4,37.9 C_VUSB.2 ; Y_XT2.2@57.975,42.275 Y_XT2.2@58.05,42.65 ; 58.125,43.025 58.2,43.4 ; v1(58.915,47.983) 58.925,47.973 59.327,47.973 59.62,47.791 60.009,47.791 62.15,45.65 62.149,45.45 ; 62.235,45.45 v1(62.235,45.699) ; C_VBUS.2 62.737,37.825 C_VUSB.2 ; U_MAIN.49@64.494,52.155 64.9,52.16 65.301,52.16 65.525,52.384 65.962,52.384 66.4,52.384 66.655,52.129 66.655,52.017 C_MCU_DVCC2.2 67.284,51.65 67.657,51.65 68.031,51.65 68.342,51.961 ; v1(69.256,61.483) 69.536,61.483 69.816,61.483 70.165,61.832 70.514,62.181 70.863,62.53 71.212,62.879 71.561,63.228 71.91,63.577 72.259,63.926 72.608,64.275 72.957,64.624 73.306,64.973 73.655,65.322 74.004,65.671 74.353,66.02 74.702,66.369 ; 75.4,68.423 75.4,68.875 75.4,69.65 76.9,71.15 77.9,71.15 78.41,70.64 R_BL_GATE_PD.2 79.287,70.4 Q_BL.2 81.498,68.189 84.348,68.189 88.863,63.675 91.681,63.675 100.775,63.675 ; C_TFT_VDDI1.2 88.91,40.4 91.91,40.4 C_TFT_VDDI2.2 92.212,39.702 92.514,40.004 92.816,40.306 93.081,40.306 v1(93.346,40.306) ; v1(94.702,40.304) 95.225,39.781 C_TFT_VCI.2 95.546,39.721 95.868,40.043 96.189,40.364 96.511,40.686 96.832,41.007 97.154,41.329 97.475,41.65 97.929,41.65 98.382,41.65 98.836,41.65 99.289,41.65 99.743,41.65 100.196,41.65 100.47,41.65 100.744,41.65 ; 101.4,46.3 101.4,46.5 ; 101.4,46.8 J_DISPLAY.17@101.4,47 ; 101.4,47.3 101.4,47.5 ; J_DISPLAY.18@101.4,47.8 101.4,48 ; 101.4,48.3 J_DISPLAY.20@101.4,48.5 ; 101.4,49 101.4,48.8 J_DISPLAY.22@101.4,49.5 ; 101.4,49.8 101.4,50.5 101.4,50.3 ; 101.4,50.8 J_DISPLAY.25@101.4,51 ; 101.4,51.3 101.4,51.5 ; 101.4,51.8 101.4,52 ; 101.4,52.3 101.4,52.5 ; 101.4,52.8 101.4,53 ; 101.4,53.3 J_DISPLAY.30@101.4,53.5 ; 101.4,53.8 101.4,54 ; 101.4,54.3 J_DISPLAY.32@101.4,54.5 ; 101.4,62.8 101.4,63 ; 101.4,63.3 J_DISPLAY.50@101.4,63.5 ; 102.1,62.7 102.4,62.6 102.4,60.275 102.275,60.15 102.4,60.15 102.65,59.9 102.65,59.15 102.9,58.9 102.9,58.65 103.15,58.4 103.15,55.9 102.9,55.65 102.9,55.4 102.839,55.339 102.615,55.339 ; 102.384,41.884 102.576,42.263 102.767,42.642 102.959,42.834 102.959,43.021 103.15,43.4 102.797,44.347 102.797,44.822 102.797,45.298 102.513,45.582 102.394,45.866
  Bottom w0.5: J_USB.18 35.058,58.977 v1(35.058,61.713) ; v1(34.401,55.325) 34.401,54.533 v1(37.239,51.695) ; v1(34.418,48.37) 34.418,50.33 v1(35.353,51.265) ; v1(39.996,61.367) 39.999,61.364 40.057,61.364 40.06,61.361 40.432,61.361 v1(40.804,61.361) ; v1(48.5,54.605) 49.595,55.7 v1(51.7,55.7) ; v1(58.723,46.038) 58.732,46.047 58.732,46.931 58.65,47.65 v1(58.915,47.983) ; v1(62.235,45.699) 62.235,51.574 v1(62.72,52.059) ; v1(68.745,52.364) 68.745,52.841 68.745,53.318 68.745,53.795 68.745,54.272 68.745,54.749 68.745,55.226 68.745,55.702 68.745,56.179 68.745,56.656 68.745,57.133 68.745,57.61 68.745,58.087 68.745,58.564 68.745,59.041 68.745,59.518 68.745,59.995 68.745,60.472 68.745,60.949 68.98,61.183 69.215,61.418 69.215,61.442 v1(69.256,61.483) ; v1(93.346,40.306) 93.348,40.304 v1(94.702,40.304)
MAIN_RESET: C_MCU_RESET.1 J_DEBUG.3 R_MCU_RESET.1 U_MAIN.76 | length 33.3
  Top w0.15: C_MCU_RESET.1 51.187,41.853 v1(51.2,41.853) ; v1(52.943,41.929) 52.89,41.982 52.89,42.15 R_MCU_RESET.1 53.394,42.904 53.584,42.904 54.65,43.971 U_MAIN.76 54.7,44.762 v1(54.7,45.748)
  Bottom w0.15: v1(51.2,41.853) 51.223,41.876 51.223,42 51.294,41.929 v1(52.943,41.929) ; J_DEBUG.3 54.05,46.401 54.567,45.884 54.567,45.881 v1(54.7,45.748)
MSP_USB_PUR: R_USB_PULLUP.1 U_MAIN.63 | length 7.5
  Top w0.15: U_MAIN.63 61.15,45.433 v1(61.307,45.765) ; R_USB_PULLUP.1 64.89,43.113 65.093,43.316 65.093,43.378 v1(65.091,43.363)
  Bottom w0.15: v1(61.307,45.765) 61.491,45.588 61.491,45.545 63.656,43.38 v1(65.091,43.363)
MSP_V18: C_V18.1 U_MAIN.67 | length 13.7
  Top w0.15: v1(53.604,40.073) 53.766,39.911 53.781,39.911 54.216,39.475 C_V18.1 ; v1(57.716,46.387) 58.697,46.383 58.886,46.354 59.143,46.183 U_MAIN.67
  Bottom w0.15: v1(53.604,40.073) 53.604,42.272 57.714,46.382 v1(57.716,46.387)
MSP_VCORE: C_VCORE.1 U_MAIN.20 | length 2.4
  Top w0.15: C_VCORE.1 49.225,57.638 U_MAIN.20
MSP_VUSB: C_VUSB.1 U_MAIN.66 | length 6.3
  Top w0.15: C_VUSB.1 58.776,39.475 60.1,40.798 59.826,41.071 59.821,43.667 U_MAIN.66
usb-dm-mcu: R_USB_DM.2 U_MAIN.64 | length 2.3
  Top w0.25: v1(60.645,43.269) 60.834,43.179 61.023,43.089 61.211,43 R_USB_DM.2 ; U_MAIN.64 60.65,44.465 60.65,44.218 60.65,43.971 60.656,43.965 v1(60.7,43.7)
  Bottom w0.25: v1(60.645,43.269) 60.651,43.366 60.747,43.461 60.703,43.693 v1(60.7,43.7)
usb-dm-phy: R_USB_DM.1 U_ESD.4 | length 30.9
  Top w0.25: U_ESD.4 38.629,52.259 39.576,52.259 40.208,51.704 43.732,48.104 v1(49.096,48.104) ; v1(52.781,47.55) 52.771,47.523 53.748,47.525 55.007,47.531 56.267,47.536 57.523,47.577 57.944,47.563 v1(59.205,47.443) ; R_USB_DM.1 61.4,41.583 61.537,41.447 61.582,41.447 v1(61.724,41.305)
  Bottom w0.25: v1(49.096,48.104) 49.135,48.065 49.255,48.065 50.114,47.221 50.643,47.233 52.436,47.182 v1(52.781,47.55) ; v1(59.205,47.443) 59.216,47.372 59.216,47.265 59.216,43.813 v1(61.724,41.305)
usb-dm-port: J_USB.7 J_USB.9 U_ESD.3 | length 6.6
  Top w0.25: v1(31.905,50.774) 31.908,50.79 32.048,50.65 J_USB.7 ; v1(31.906,51.567) 32.794,51.595 J_USB.9 35.058,51.657 35.763,52.35 U_ESD.3
  Bottom w0.25: v1(31.905,50.774) 31.905,51.498 31.874,51.529 31.874,51.591 v1(31.906,51.567)
usb-dp-mcu: R_USB_DP.2 R_USB_PULLUP.2 U_MAIN.62 | length 7.3
  Top w0.188: 61.85,43.85 61.95,43.75 62.05,43.75 62.187,43.597 62.324,43.444 62.462,43.291
  Top w0.219: 61.75,43.95 61.85,43.85
  Top w0.25: U_MAIN.62 61.701,44.453 61.717,44.286 61.734,44.118 61.75,43.95 ; 62.462,43.291 62.6,43.138 R_USB_DP.2 63.428,43.74 65.257,43.754 65.91,43.085 R_USB_PULLUP.2
usb-dp-phy: R_USB_DP.1 U_ESD.6 | length 33.2
  Top w0.25: U_ESD.6 41.867,47.121 v1(49.184,47.121) ; v1(51.712,46.812) 51.678,46.879 51.678,46.955 51.767,47.044 51.752,47.681 52.56,48.468 v1(59.684,48.466) ; R_USB_DP.1 63.208,41.89 63.723,42.404 v1(63.689,42.438)
  Bottom w0.25: v1(49.184,47.121) 49.226,47.079 49.266,47.079 49.467,46.864 v1(51.712,46.812) ; v1(59.684,48.466) 59.763,48.384 59.763,48.321 59.858,48.225 59.848,45.851 59.923,45.54 63.281,42.437 v1(63.689,42.438)
usb-dp-port: J_USB.8 J_USB.10 U_ESD.1 | length 7.1
  Top w0.25: J_USB.10 31.953,52.164 31.338,51.552 31.74,51.166 J_USB.8 34.792,51.123 35.504,50.442 36.259,50.454 U_ESD.1
USB_CC1: J_USB.6 R_CC1.1 | length 12.8
  Top w0.15: J_USB.6 34.3,50.15 v1(35.315,49.135) ; R_CC1.1 34.89,39.822 34.945,39.877 34.945,39.945 v1(35,40)
  Bottom w0.15: v1(35,40) 35.339,40.339 35.339,49.108 35.339,49.111 v1(35.315,49.135)
USB_CC2: J_USB.12 R_CC2.1 | length 17.4
  Top w0.15: J_USB.12 32.899,53.2 v1(33.8,53.2) ; v1(34.532,43.371) 34.458,43.197 34.458,43.186 38.245,39.4 R_CC2.1
  Bottom w0.15: v1(33.8,53.2) 33.782,53.182 33.782,43.873 v1(34.532,43.371)
VBUS5: C_LDO_IN.1 C_VBUS.1 J_USB.3 J_USB.4 J_USB.13 J_USB.14 R_BL1.1 R_BL2.1 R_BL3.1 R_BL4.1 U_ESD.5 U_LDO.1 U_LDO.3 U_MAIN.65 | length 121.2
  Top w0.25: U_MAIN.65 60.15,45.45 60.15,45.369 60.15,45.275 60.15,45.181 60.15,45.087 60.15,44.994 60.15,44.9 60.15,44.806 U_MAIN.65
  Top w0.3: 32.181,53.666 32.556,53.65 J_USB.14 32.849,53.8 ; J_USB.4@32.199,49.15 32.468,49.15 J_USB.4 ; J_USB.3@32.849,49 J_USB.4 ; J_USB.13 32.943,53.95 J_USB.13@33.037,53.95 ; J_USB.4@33.311,49.15 J_USB.4
  Top w0.312: 60.228,43.275 60.228,43.119 60.408,42.916 60.587,42.713
  Top w0.325: v1(52.217,47.583) 52.442,47.302 52.667,47.021 ; U_MAIN.65@60.19,43.975 60.202,43.754 60.228,43.275
  Top w0.33: U_MAIN.65 60.176,44.233 U_MAIN.65@60.19,43.975
  Top w0.375: 31.798,49.554 32.087,49.15 J_USB.4@32.199,49.15
  Top w0.437: 31.712,53.197 31.838,53.588 32.056,53.588 32.181,53.666
  Top w0.45: 31.678,53.066 31.712,53.197 ; 56.421,47.036 56.891,47.038 57.067,47.098 57.587,47.088
  Top w0.475: J_USB.13@33.037,53.95 J_USB.13@33.476,53.878 ; J_USB.4@33.311,49.15 33.772,49.15
  Top w0.5: 31.678,53.066 31.386,52.774 31.094,52.481 30.802,52.189 30.802,51.78 30.802,51.37 30.802,50.96 30.802,50.55 31.134,50.218 31.466,49.886 31.798,49.554 ; J_USB.3 J_USB.4@32.849,49 ; J_USB.13@32.849,53.8 J_USB.13 ; J_USB.13@33.476,53.878 33.916,53.806 36.425,56.316 36.425,59.512 U_LDO.1 ; C_LDO_IN.1 35.373,60.475 35.436,60.537 U_LDO.1 ; 33.772,49.15 34.132,49.064 34.492,48.978 34.852,48.893 35.275,48.4 35.8,48.4 37.4,50 37.4,50.8 37.8,51.2 U_ESD.5 38.963,51.4 39.388,51.4 39.814,51.4 40.158,51.056 40.502,50.712 v1(40.611,50.603) ; U_LDO.3 39,59.6 38.4,59.4 37.8,59.6 U_LDO.1 ; 52.667,47.021 53.136,47.023 53.606,47.025 54.075,47.027 54.544,47.029 55.013,47.031 55.483,47.033 55.952,47.035 56.421,47.036 ; 57.587,47.088 57.829,47.042 58.299,47.044 59.4,46.65 60.15,45.9 60.15,45.45 60.15,45.462 60.15,45.65 60.338,45.838 v1(60.42,45.838) ; 60.587,42.713 60.587,39.813 C_VBUS.1 ; v1(61.011,48.883) 61.454,48.883 61.898,48.883 62.341,48.883 62.784,48.883 62.942,48.725 62.954,48.725 v1(62.989,48.69) ; v1(80.349,62.602) 80.349,64.175 v1(81.044,64.87) ; v1(82.404,65.286) 83.411,65.286 v1(84.821,66.696) ; v1(85.075,68.4) 85.075,68.987 R_BL1.1 85.487,69.487 86.15,70.15 86.15,70.4 86.4,70.65 88.15,70.65 89.4,69.4 R_BL2.1 89.487,69.487 90.15,70.15 90.15,70.4 90.4,70.65 92.15,70.65 93.4,69.4 R_BL3.1 93.487,70.65 96.238,70.65 R_BL4.1
  Bottom w0.325: 51.769,47.923 51.773,47.923 52.109,47.588 52.159,47.587 v1(52.217,47.583)
  Bottom w0.35: v1@82.354,65.236 v1(82.404,65.286)
  Bottom w0.5: v1(40.611,50.603) 49.09,50.603 50.095,49.598 51.769,47.923 ; v1(60.42,45.838) 60.42,48.292 v1(61.011,48.883) ; v1(62.989,48.69) 63.443,48.69 63.897,48.69 64.351,48.69 64.805,48.69 65.259,48.69 65.713,48.69 66.167,48.69 66.621,48.69 66.972,49.041 67.323,49.392 67.675,49.743 68.026,50.094 68.377,50.445 68.728,50.797 69.079,51.148 69.43,51.499 69.781,51.85 70.132,52.201 70.483,52.552 70.834,52.903 71.186,53.254 71.537,53.605 71.888,53.956 72.239,54.308 72.59,54.659 72.941,55.01 73.292,55.361 73.643,55.712 73.994,56.063 74.345,56.414 74.697,56.765 75.048,57.116 75.399,57.467 75.75,57.819 76.101,58.17 76.452,58.521 76.803,58.872 77.154,59.223 77.505,59.574 77.856,59.925 78.208,60.276 78.559,60.627 78.91,60.978 79.261,61.33 79.612,61.681 79.963,62.032 80.314,62.383 80.314,62.567 v1(80.349,62.602) ; v1(81.044,64.87) 81.516,64.87 81.988,64.87 82.171,65.053 v1@82.354,65.236 ; v1(84.821,66.696) 84.821,68.146 v1(85.075,68.4)
VCC_3V3: C_3V3_BULK.1 C_LDO_OUT.1 C_MCU_AVCC.1 C_MCU_DVCC1.1 C_MCU_DVCC2.1 C_TFT_VCI.1 C_TFT_VDDI1.1 C_TFT_VDDI2.1 J_DEBUG.1 J_DISPLAY.7 J_DISPLAY.8 J_DISPLAY.9 J_DISPLAY.35 J_DISPLAY.40 J_DISPLAY.41 J_DISPLAY.42 R_DISPLAY_CS.2 R_DISPLAY_RESET.2 R_MCU_RESET.2 U_LDO.5 U_MAIN.11 U_MAIN.18 U_MAIN.50 | length 144.1
  Top w0.12: 40.39,61.48 40.397,61.207 40.403,60.935 ; 49.793,46.861 49.792,46.519 49.792,46.177 49.791,45.835 49.803,46.066
  Top w0.125: 49.793,46.861 49.793,47.203 49.794,47.545 49.795,47.887 49.795,48.229 49.796,48.571 49.796,48.914 49.797,49.256
  Top w0.138: 49.799,50.966 49.8,51.308 49.801,51.65 ; 49.803,46.066 49.815,46.298 ; 52.435,42.33 52.408,42.191 52.459,42.005 52.51,41.819
  Top w0.15: 40.39,61.48 40.416,61.576 40.622,61.782 ; 49.797,49.256 49.797,49.598 49.798,49.94 49.798,50.282 49.799,50.624 49.799,50.966 ; 49.801,51.65 49.815,51.548
  Top w0.162: 40.403,60.935 40.41,60.662 ; 49.815,46.298 50.053,46.059 ; 52.435,42.33 52.435,42.667 52.435,43.004 52.435,43.341
  Top w0.175: 52.51,41.819 52.535,41.846 52.667,41.723 52.8,41.6 53.1,41.55
  Top w0.2: 40.622,61.782 40.829,61.988
  Top w0.212: 53.1,41.55 53.262,41.752
  Top w0.225: 53.262,41.752 53.478,41.968
  Top w0.238: J_DISPLAY.40@101.805,58.547 102.107,58.547 102.275,58.4 102.275,58.072 102.275,57.744 102.275,57.416 102.275,57.088 102.275,56.759 102.275,56.431 102.056,56.213
  Top w0.25: U_MAIN.18@49.975,55.075 U_MAIN.18@50.125,55.075 ; U_MAIN.18@49.975,55.15 50.056,55.15 50.15,55.15 50.244,55.15 50.337,55.15 50.431,55.15 50.525,55.15 50.619,55.15 U_MAIN.18 50.589,55.027 50.356,55.027 U_MAIN.18@50.343,55.054 ; U_MAIN.11@49.976,51.65 50.057,51.65 50.15,51.65 50.244,51.65 50.338,51.65 50.432,51.65 50.525,51.65 50.619,51.65 U_MAIN.11 ; U_MAIN.11@50.182,51.65 50.447,51.65 U_MAIN.11 ; U_MAIN.11@50.376,51.65 U_MAIN.11 ; 51.45,51.65 51.369,51.65 51.275,51.65 51.181,51.65 51.088,51.65 50.994,51.65 50.9,51.65 50.806,51.65 U_MAIN.11 ; 63.338,51.612 63.351,51.65 63.432,51.65 63.525,51.65 63.619,51.65 63.713,51.65 63.807,51.65 63.9,51.65 63.994,51.65 U_MAIN.50 64.182,51.65 U_MAIN.50@64.276,51.65
  Top w0.288: J_DISPLAY.40 101.503,58.547 J_DISPLAY.40@101.805,58.547
  Top w0.29: U_MAIN.50@64.276,51.65 64.37,51.608 U_MAIN.50@64.825,51.621
  Top w0.3: U_MAIN.18@50.125,55.075 U_MAIN.18@50.343,55.054 ; J_DISPLAY.7@100.931,42.15 101.025,42.15 101.119,42.15 101.213,42.15 101.306,42.15 J_DISPLAY.7 101.4,42.3 ; J_DISPLAY.8@101.4,42.5 J_DISPLAY.8 J_DISPLAY.8@101.4,42.8 ; J_DISPLAY.9@101.4,43 J_DISPLAY.9 101.65,43.15 101.9,43.15 J_DISPLAY.9@102.025,43.15 ; J_DISPLAY.40 101.4,58.8 ; 101.4,59 J_DISPLAY.41 J_DISPLAY.41@101.4,59.3 ; 101.4,59.5 J_DISPLAY.42 ; J_DISPLAY.35@101.728,56.181 J_DISPLAY.35 101.724,56.15 102.048,56.15
  Top w0.312: v1@102.299,55.901 v1(102.4,55.8)
  Top w0.35: U_LDO.5 37.717,58.41 37.984,58.557 38.251,58.704 38.4,58.138 38.925,57.262 39.625,57.262 39.975,57.438 39.975,59.013 39.539,59.513 39.6,59.5 39.625,59.45 39.975,59.8 40.197,60.171 40.416,60.39 40.41,60.662 ; 40.829,61.988 41.035,62.194 41.241,62.4 C_LDO_OUT.1 41.76,62.585 41.945,62.77 42.13,62.955 42.311,62.955 42.491,62.955 42.493,62.955 42.6,63.125 43.475,63.3 45.184,62.4 C_3V3_BULK.1 ; v1(46.607,60.405) 45.85,61 45.584,61.663 C_3V3_BULK.1 ; C_MCU_AVCC.1 49.963,51.65 49.975,51.65 ; v1(48.571,55.956) 48.695,55.832 48.746,55.832 48.91,55.668 C_MCU_DVCC1.1 49.963,55.15 U_MAIN.18@49.975,55.15 ; J_DEBUG.1 48.97,65.882 C_3V3_BULK.1 ; 49.815,51.548 49.917,51.65 U_MAIN.11@50.182,51.65 ; 49.975,55.075 49.775,55.075 49.51,54.515 49.313,54.318 49.313,53.994 49.313,53.671 49.313,53.347 49.313,53.023 49.313,52.7 49.313,52.376 49.555,52.134 49.775,51.75 U_MAIN.11@50.376,51.65 ; 50.053,46.059 50.291,45.821 50.53,45.583 50.768,45.345 51.006,45.107 51.244,44.868 51.482,44.63 51.721,44.392 51.959,44.154 52.4,43.7 52.435,43.677 52.435,43.341 ; 51.45,51.65 51.463,51.648 63.338,51.612 ; 53.478,41.968 53.694,42.184 R_MCU_RESET.2 ; 64.825,51.621 65.62,51.643 C_MCU_DVCC2.1 65.89,48.376 75.796,38.47 75.98,38.47 R_DISPLAY_CS.2 78.089,40.583 78.671,40.606 78.75,40.601 R_DISPLAY_RESET.2 80.065,39.245 v1(82.596,39.25) ; v1(83.431,38.683) 83.448,38.666 84.181,39.4 C_TFT_VDDI1.1 88.13,39.16 88.37,38.92 88.415,38.92 88.153,38.913 87.89,38.905 88.21,38.905 88.45,38.8 88.9,38.5 89.325,38.8 89.807,38.905 89.611,38.913 89.415,38.92 89.655,39.16 89.895,39.4 90.227,39.4 90.558,39.4 C_TFT_VDDI2.1 91.425,38.8 91.9,38.5 92.322,38.8 92.992,39.4 93.284,39.4 C_TFT_VCI.1 94.224,40.071 94.075,39.799 94.15,40.9 95.775,42.15 97.548,42.195 98.877,42.2 100.676,42.2 J_DISPLAY.7@100.931,42.15 ; 101.4,42.3 101.4,42.5 ; J_DISPLAY.8@101.4,42.8 101.4,43 ; 101.4,58.8 101.4,59 ; 101.4,59.3 101.4,59.5 ; J_DISPLAY.35@101.728,56.181 102.056,56.213 ; 102.025,43.15 102.15,43.15 102.275,43.275 v1(102.4,43.4) ; 102.048,56.15 102.275,55.95 102.297,55.901 v1@102.299,55.901
  Bottom w0.35: v1(46.607,60.405) 46.637,60.379 48.571,58.445 v1(48.571,55.956) ; v1(82.596,39.25) 82.643,39.203 82.648,39.203 83.168,38.683 v1(83.431,38.683) ; v1(102.4,43.4) 102.4,43.541 102.4,43.881 102.4,44.222 102.4,44.562 102.4,44.903 102.4,45.243 102.4,45.584 102.4,45.924 102.4,46.265 102.4,46.606 102.4,46.946 102.4,47.287 102.4,47.627 102.4,47.968 102.4,48.308 102.4,48.649 102.4,48.989 102.4,49.33 102.4,49.67 102.4,50.011 102.4,50.351 102.4,50.692 102.4,51.032 102.4,51.373 102.4,51.714 102.4,52.054 102.4,52.395 102.4,52.735 102.4,53.076 102.4,53.416 102.4,53.757 102.4,54.097 102.4,54.438 102.4,54.778 102.4,55.119 102.4,55.459 v1(102.4,55.8)
XT2_IN: U_MAIN.69 Y_XT2.1 | length 5.8
  Top w0.15: U_MAIN.69 58.2,44.762 v1(58.2,45.971) ; v1(58.776,43.351) 58.806,43.321 59.4,42.727 Y_XT2.1
  Bottom w0.15: v1(58.2,45.971) 58.2,45.861 58.776,45.285 v1(58.776,43.351)
XT2_OUT: U_MAIN.70 Y_XT2.3 | length 3.3
  Top w0.15: Y_XT2.3 56.4,42.746 57.57,43.915 57.57,44.632 U_MAIN.70
pads on no net: J_DISPLAY.11 J_DISPLAY.12 J_DISPLAY.13 J_DISPLAY.14 J_DISPLAY.44 J_DISPLAY.45 J_DISPLAY.46 J_DISPLAY.47 J_DISPLAY.51 J_DISPLAY.52 J_USB.5 J_USB.11 J_USB.NPTH-1 J_USB.NPTH-2 U_LDO.4 U_MAIN.1 U_MAIN.2 U_MAIN.3 U_MAIN.4 U_MAIN.5 U_MAIN.6 U_MAIN.7 U_MAIN.8 U_MAIN.9 U_MAIN.10 U_MAIN.12 U_MAIN.13 U_MAIN.15 U_MAIN.16 U_MAIN.17 U_MAIN.21 U_MAIN.22 U_MAIN.25 U_MAIN.26 U_MAIN.27 U_MAIN.28 U_MAIN.29 U_MAIN.30 U_MAIN.31 U_MAIN.32 U_MAIN.33 U_MAIN.34 U_MAIN.35 U_MAIN.36 U_MAIN.45 U_MAIN.46 U_MAIN.47 U_MAIN.48 U_MAIN.51 U_MAIN.52 U_MAIN.53 U_MAIN.54 U_MAIN.55 U_MAIN.56 U_MAIN.57 U_MAIN.58 U_MAIN.59 U_MAIN.60 U_MAIN.72 U_MAIN.73 U_MAIN.74 U_MAIN.75 U_MAIN.77 U_MAIN.78 U_MAIN.79 U_MAIN.80

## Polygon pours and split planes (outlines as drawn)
GND on Bottom (solid): 107.1,77.1 25.7,77.1 25.7,25.7 107.1,25.7
GND on Bottom (solid): 49.479,47.389 49.517,47.343 49.554,47.274 49.565,47.235 49.611,47.186 49.687,47.184
GND on Bottom (solid): 64.015,64.791 64.015,63.174 64.048,63.184 64.116,63.191 64.116,64.658 64.093,64.677 64.043,64.738
GND on Bottom (solid): 64.51,62.687 64.495,62.639 64.458,62.57 64.409,62.509 64.348,62.459 64.279,62.422 64.204,62.4 64.126,62.392 64.048,62.4 64.015,62.409 64.015,62.383 64.016,62.383 64.094,62.375 64.169,62.353 64.238,62.316 64.299,62.266 64.349,62.205 64.369,62.166 64.51,62.307
GND on Bottom (solid): 66.454,68.594 66.454,68.021 66.478,67.992 66.502,67.947 66.502,68.545 66.479,68.564
GND on Bottom (solid): 80.814,62.818 80.741,62.818 80.765,62.774 80.781,62.722 80.804,62.799

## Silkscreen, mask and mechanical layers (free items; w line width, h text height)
Top Overlay:
  text "2L • BOTTOM GND POUR" at 48.4,75.4 h0.48
  text "ER-CON50HT-1 • 4-WIRE SPI" at 84.4,75.4 h0.55
  text "ER-TFT028A2-4" at 81.4,28.9 h0.58
  text "QUICK CONFIGURE • SCREEN" at 66.4,27.4 h0.72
